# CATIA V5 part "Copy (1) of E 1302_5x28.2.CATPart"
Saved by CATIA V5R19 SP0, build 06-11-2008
Part number: Copy (1) of E 1302_5x28.2
Nomenclature: E 1302_5x28
Source: Unknown
Description: PART-E 1302_5x28-DESC
Bounding box of the stored display mesh (mm): x -2.5 to 2.5, y -2.5 to 2.5, z 0 to 28
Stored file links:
  C:\Users\jsmid\Desktop\DP_Smidak_Forma LEGO\Copy (1) of E 1302_5x28.2.CATPart
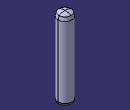
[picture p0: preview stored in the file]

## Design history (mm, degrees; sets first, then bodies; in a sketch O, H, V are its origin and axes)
Body1 "E 1302_5x28" (main body)
  Solid1: solid without history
